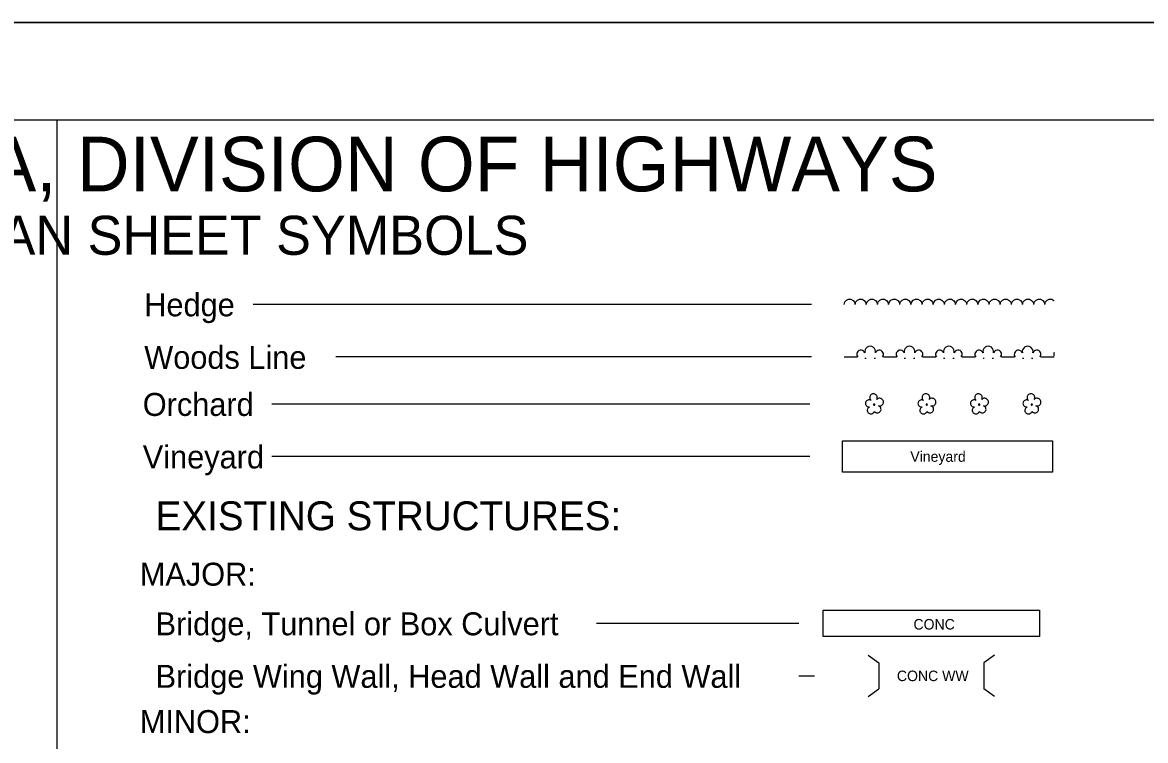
# Model space of a CAD drawing. Extents: x 754056.72 to 754059.56, y 596603.78 to 596605.61.
# Drawn here: x 754058.119 to 754058.839, y 596605.152 to 596605.612 of the extents above; entities that cross this region are included whole.
import ezdxf

# ---------------------------------------------------------------- set-up
doc = ezdxf.new("R2010")
doc.units = 0
for name, color, linetype in [('Sheet_Plan', 7, 'Continuous'), ('Sheet_Plot_Border_Outside_CELL', 7, 'Continuous'), ('Sheet_Symbology', 7, 'Continuous'), ('z - Construction', 7, 'Continuous')]:
    doc.layers.add(name, color=color, linetype=linetype)

msp = doc.modelspace()

# ---------------------------------------------------------------- linework, layer by layer
at = {"layer": 'Sheet_Plan'}
msp.add_line((754059.49567, 596605.54909), (754056.78733, 596605.54909), dxfattribs=at)
at = {"layer": 'Sheet_Plot_Border_Outside_CELL'}
msp.add_lwpolyline([(754056.72484, 596605.61159), (754059.55817, 596605.61159), (754059.55817, 596603.77826), (754056.72484, 596603.77826)], close=True, dxfattribs=at)
at = {"layer": 'Sheet_Symbology'}
for p, q in [((754058.64563, 596605.43106), (754058.64614, 596605.43266)), ((754058.64614, 596605.43266), (754058.64714, 596605.43375)), ((754058.64714, 596605.43375), (754058.64849, 596605.43451)), ((754058.64849, 596605.43451), (754058.65009, 596605.43451)), ((754058.65009, 596605.43451), (754058.65143, 596605.43367)), ((754058.65143, 596605.43367), (754058.65236, 596605.43258)), ((754058.65236, 596605.43258), (754058.65269, 596605.43115)), ((754058.65278, 596605.43106), (754058.65328, 596605.43266)), ((754058.65328, 596605.43266), (754058.65429, 596605.43375)), ((754058.65429, 596605.43375), (754058.65564, 596605.43451)), ((754058.65564, 596605.43451), (754058.65723, 596605.43451)), ((754058.65723, 596605.43451), (754058.65858, 596605.43367)), ((754058.65858, 596605.43367), (754058.6595, 596605.43258)), ((754058.6595, 596605.43258), (754058.65984, 596605.43115)), ((754058.65992, 596605.43106), (754058.66043, 596605.43266)), ((754058.66043, 596605.43266), (754058.66144, 596605.43375)), ((754058.66144, 596605.43375), (754058.66278, 596605.43451)), ((754058.66278, 596605.43451), (754058.66438, 596605.43451)), ((754058.66438, 596605.43451), (754058.66573, 596605.43367)), ((754058.66573, 596605.43367), (754058.66665, 596605.43258)), ((754058.66665, 596605.43258), (754058.66699, 596605.43115)), ((754058.66707, 596605.43106), (754058.66758, 596605.43266)), ((754058.66758, 596605.43266), (754058.66858, 596605.43375)), ((754058.66858, 596605.43375), (754058.66993, 596605.43451)), ((754058.66993, 596605.43451), (754058.67153, 596605.43451)), ((754058.67153, 596605.43451), (754058.67287, 596605.43367)), ((754058.67287, 596605.43367), (754058.6738, 596605.43258)), ((754058.6738, 596605.43258), (754058.67413, 596605.43115)), ((754058.67422, 596605.43106), (754058.67472, 596605.43266)), ((754058.67472, 596605.43266), (754058.67573, 596605.43375)), ((754058.67573, 596605.43375), (754058.67708, 596605.43451)), ((754058.67708, 596605.43451), (754058.67867, 596605.43451)), ((754058.67867, 596605.43451), (754058.68002, 596605.43367)), ((754058.68002, 596605.43367), (754058.68094, 596605.43258)), ((754058.68094, 596605.43258), (754058.68128, 596605.43115)), ((754058.68136, 596605.43106), (754058.68187, 596605.43266)), ((754058.68187, 596605.43266), (754058.68288, 596605.43375)), ((754058.68288, 596605.43375), (754058.68422, 596605.43451)), ((754058.68422, 596605.43451), (754058.68582, 596605.43451)), ((754058.68582, 596605.43451), (754058.68717, 596605.43367)), ((754058.68717, 596605.43367), (754058.68809, 596605.43258)), ((754058.68809, 596605.43258), (754058.68843, 596605.43115)), ((754058.68851, 596605.43106), (754058.68902, 596605.43266)), ((754058.68902, 596605.43266), (754058.69002, 596605.43375)), ((754058.69002, 596605.43375), (754058.69137, 596605.43451)), ((754058.69137, 596605.43451), (754058.69297, 596605.43451)), ((754058.69297, 596605.43451), (754058.69431, 596605.43367)), ((754058.69431, 596605.43367), (754058.69524, 596605.43258)), ((754058.69524, 596605.43258), (754058.69557, 596605.43115)), ((754058.69566, 596605.43106), (754058.69616, 596605.43266)), ((754058.69616, 596605.43266), (754058.69717, 596605.43375)), ((754058.69717, 596605.43375), (754058.69852, 596605.43451)), ((754058.69852, 596605.43451), (754058.70011, 596605.43451)), ((754058.70011, 596605.43451), (754058.70146, 596605.43367)), ((754058.70146, 596605.43367), (754058.70238, 596605.43258)), ((754058.70238, 596605.43258), (754058.70272, 596605.43115)), ((754058.7028, 596605.43106), (754058.70331, 596605.43266)), ((754058.70331, 596605.43266), (754058.70432, 596605.43375)), ((754058.70432, 596605.43375), (754058.70566, 596605.43451)), ((754058.70566, 596605.43451), (754058.70726, 596605.43451)), ((754058.70726, 596605.43451), (754058.70861, 596605.43367)), ((754058.70861, 596605.43367), (754058.70953, 596605.43258)), ((754058.70953, 596605.43258), (754058.70987, 596605.43115)), ((754058.70995, 596605.43106), (754058.71046, 596605.43266)), ((754058.71046, 596605.43266), (754058.71146, 596605.43375)), ((754058.71146, 596605.43375), (754058.71281, 596605.43451)), ((754058.71281, 596605.43451), (754058.71441, 596605.43451)), ((754058.71441, 596605.43451), (754058.71575, 596605.43367)), ((754058.71575, 596605.43367), (754058.71668, 596605.43258)), ((754058.71668, 596605.43258), (754058.71701, 596605.43115)), ((754058.7171, 596605.43106), (754058.7176, 596605.43266)), ((754058.7176, 596605.43266), (754058.71861, 596605.43375)), ((754058.71861, 596605.43375), (754058.71996, 596605.43451)), ((754058.71996, 596605.43451), (754058.72155, 596605.43451)), ((754058.72155, 596605.43451), (754058.7229, 596605.43367)), ((754058.7229, 596605.43367), (754058.72382, 596605.43258)), ((754058.72382, 596605.43258), (754058.72416, 596605.43115)), ((754058.72424, 596605.43106), (754058.72475, 596605.43266)), ((754058.72475, 596605.43266), (754058.72576, 596605.43375)), ((754058.72576, 596605.43375), (754058.7271, 596605.43451)), ((754058.7271, 596605.43451), (754058.7287, 596605.43451)), ((754058.7287, 596605.43451), (754058.73005, 596605.43367)), ((754058.73005, 596605.43367), (754058.73097, 596605.43258)), ((754058.73097, 596605.43258), (754058.73131, 596605.43115)), ((754058.73139, 596605.43106), (754058.7319, 596605.43266)), ((754058.7319, 596605.43266), (754058.7329, 596605.43375)), ((754058.7329, 596605.43375), (754058.73425, 596605.43451)), ((754058.73425, 596605.43451), (754058.73585, 596605.43451)), ((754058.73585, 596605.43451), (754058.73719, 596605.43367)), ((754058.73719, 596605.43367), (754058.73812, 596605.43258)), ((754058.73812, 596605.43258), (754058.73845, 596605.43115)), ((754058.73854, 596605.43106), (754058.73904, 596605.43266)), ((754058.73904, 596605.43266), (754058.74005, 596605.43375)), ((754058.74005, 596605.43375), (754058.7414, 596605.43451)), ((754058.7414, 596605.43451), (754058.74299, 596605.43451)), ((754058.74299, 596605.43451), (754058.74434, 596605.43367)), ((754058.74434, 596605.43367), (754058.74526, 596605.43258)), ((754058.74526, 596605.43258), (754058.7456, 596605.43115)), ((754058.74568, 596605.43106), (754058.74619, 596605.43266)), ((754058.74619, 596605.43266), (754058.7472, 596605.43375)), ((754058.7472, 596605.43375), (754058.74854, 596605.43451)), ((754058.74854, 596605.43451), (754058.75014, 596605.43451)), ((754058.75014, 596605.43451), (754058.75149, 596605.43367)), ((754058.75149, 596605.43367), (754058.75241, 596605.43258)), ((754058.75241, 596605.43258), (754058.75275, 596605.43115)), ((754058.75283, 596605.43106), (754058.75334, 596605.43266)), ((754058.75334, 596605.43266), (754058.75434, 596605.43375)), ((754058.75434, 596605.43375), (754058.75569, 596605.43451)), ((754058.75569, 596605.43451), (754058.75729, 596605.43451)), ((754058.75729, 596605.43451), (754058.75863, 596605.43367)), ((754058.75863, 596605.43367), (754058.75956, 596605.43258)), ((754058.75956, 596605.43258), (754058.75989, 596605.43115)), ((754058.75998, 596605.43106), (754058.76048, 596605.43266)), ((754058.76048, 596605.43266), (754058.76149, 596605.43375)), ((754058.76149, 596605.43375), (754058.76284, 596605.43451)), ((754058.76284, 596605.43451), (754058.76443, 596605.43451)), ((754058.76443, 596605.43451), (754058.76578, 596605.43367)), ((754058.76578, 596605.43367), (754058.7667, 596605.43258)), ((754058.7667, 596605.43258), (754058.76704, 596605.43115)), ((754058.76712, 596605.43106), (754058.76763, 596605.43266)), ((754058.76763, 596605.43266), (754058.76864, 596605.43375)), ((754058.76864, 596605.43375), (754058.76998, 596605.43451)), ((754058.76998, 596605.43451), (754058.77158, 596605.43451)), ((754058.77158, 596605.43451), (754058.77293, 596605.43367)), ((754058.77293, 596605.43367), (754058.77385, 596605.43258)), ((754058.77385, 596605.43258), (754058.77419, 596605.43115)), ((754058.77427, 596605.43106), (754058.77478, 596605.43266)), ((754058.77478, 596605.43266), (754058.77578, 596605.43375)), ((754058.77578, 596605.43375), (754058.77713, 596605.43451)), ((754058.77713, 596605.43451), (754058.77873, 596605.43451)), ((754058.77873, 596605.43451), (754058.78007, 596605.43367)), ((754058.78007, 596605.43367), (754058.78016, 596605.43359)), ((754058.62479, 596605.43106), (754058.26714, 596605.43106)), ((754058.62479, 596605.39743), (754058.32022, 596605.39743)), ((754058.64563, 596605.39743), (754058.65404, 596605.39743)), ((754058.659, 596605.39659), (754058.65984, 596605.39659)), ((754058.66489, 596605.39659), (754058.66573, 596605.39659)), ((754058.67085, 596605.39743), (754058.67926, 596605.39743)), ((754058.68422, 596605.39659), (754058.68506, 596605.39659)), ((754058.69011, 596605.39659), (754058.69095, 596605.39659)), ((754058.69608, 596605.39743), (754058.70449, 596605.39743)), ((754058.70945, 596605.39659), (754058.71029, 596605.39659)), ((754058.71533, 596605.39659), (754058.71617, 596605.39659)), ((754058.7213, 596605.39743), (754058.72971, 596605.39743)), ((754058.73467, 596605.39659), (754058.73551, 596605.39659)), ((754058.74056, 596605.39659), (754058.7414, 596605.39659)), ((754058.74653, 596605.39743), (754058.75493, 596605.39743)), ((754058.75989, 596605.39659), (754058.76073, 596605.39659)), ((754058.76578, 596605.39659), (754058.76662, 596605.39659)), ((754058.77175, 596605.39743), (754058.78016, 596605.39743)), ((754058.62384, 596605.36729), (754058.27923, 596605.36729)), ((754058.62384, 596605.33366), (754058.27923, 596605.33366)), ((754058.61659, 596605.22687), (754058.48716, 596605.22687)), ((754058.66106, 596605.20646), (754058.66796, 596605.20164)), ((754058.66796, 596605.20164), (754058.66796, 596605.18483)), ((754058.74211, 596605.20646), (754058.73522, 596605.20164)), ((754058.73522, 596605.20164), (754058.73522, 596605.18483)), ((754058.61659, 596605.19323), (754058.62665, 596605.19323)), ((754058.66106, 596605.18001), (754058.66796, 596605.18483)), ((754058.74211, 596605.18001), (754058.73522, 596605.18483))]:
    msp.add_line(p, q, dxfattribs=at)
for points in [[(754058.66663, 596605.37023), (754058.66688, 596605.37073), (754058.66696, 596605.37124), (754058.66688, 596605.37174), (754058.66679, 596605.37225), (754058.66654, 596605.37267), (754058.66629, 596605.37309), (754058.66587, 596605.37342), (754058.66545, 596605.37368), (754058.66486, 596605.37384), (754058.66444, 596605.37384), (754058.66393, 596605.37376), (754058.66343, 596605.37359), (754058.66301, 596605.37334), (754058.66259, 596605.373), (754058.66234, 596605.3725), (754058.66217, 596605.37208), (754058.66208, 596605.37157), (754058.66208, 596605.37107), (754058.66217, 596605.37057), (754058.66242, 596605.37014), (754058.66276, 596605.36964), (754058.66234, 596605.36989), (754058.66183, 596605.36998), (754058.66133, 596605.36998), (754058.66091, 596605.36981), (754058.66049, 596605.36964), (754058.66007, 596605.3693), (754058.65973, 596605.36897), (754058.65948, 596605.36855), (754058.65939, 596605.36813), (754058.65931, 596605.36754), (754058.65939, 596605.36712), (754058.65956, 596605.3667), (754058.6599, 596605.36628), (754058.66015, 596605.36594), (754058.66057, 596605.36569), (754058.66108, 596605.36544), (754058.6615, 596605.36535), (754058.662, 596605.36535), (754058.66158, 596605.36518), (754058.66116, 596605.36485), (754058.66091, 596605.36451), (754058.66074, 596605.36401), (754058.66057, 596605.3635), (754058.66057, 596605.36308), (754058.66066, 596605.36258), (754058.66091, 596605.36216), (754058.66116, 596605.36174), (754058.6615, 596605.3614), (754058.66192, 596605.36115), (754058.66234, 596605.36098), (754058.66284, 596605.36098), (754058.66335, 596605.36098), (754058.66377, 596605.36106), (754058.66419, 596605.3614), (754058.66461, 596605.36165), (754058.66503, 596605.36241)], [(754058.70026, 596605.37023), (754058.70051, 596605.37073), (754058.70059, 596605.37124), (754058.70051, 596605.37174), (754058.70042, 596605.37225), (754058.70017, 596605.37267), (754058.69992, 596605.37309), (754058.6995, 596605.37342), (754058.69908, 596605.37368), (754058.69849, 596605.37384), (754058.69807, 596605.37384), (754058.69757, 596605.37376), (754058.69706, 596605.37359), (754058.69664, 596605.37334), (754058.69622, 596605.373), (754058.69597, 596605.3725), (754058.6958, 596605.37208), (754058.69572, 596605.37157), (754058.69572, 596605.37107), (754058.6958, 596605.37057), (754058.69605, 596605.37014), (754058.69639, 596605.36964), (754058.69597, 596605.36989), (754058.69546, 596605.36998), (754058.69496, 596605.36998), (754058.69454, 596605.36981), (754058.69412, 596605.36964), (754058.6937, 596605.3693), (754058.69336, 596605.36897), (754058.69311, 596605.36855), (754058.69303, 596605.36813), (754058.69294, 596605.36754), (754058.69303, 596605.36712), (754058.69319, 596605.3667), (754058.69353, 596605.36628), (754058.69378, 596605.36594), (754058.6942, 596605.36569), (754058.69471, 596605.36544), (754058.69513, 596605.36535), (754058.69563, 596605.36535), (754058.69521, 596605.36518), (754058.69479, 596605.36485), (754058.69454, 596605.36451), (754058.69437, 596605.36401), (754058.6942, 596605.3635), (754058.6942, 596605.36308), (754058.69429, 596605.36258), (754058.69454, 596605.36216), (754058.69479, 596605.36174), (754058.69513, 596605.3614), (754058.69555, 596605.36115), (754058.69597, 596605.36098), (754058.69647, 596605.36098), (754058.69698, 596605.36098), (754058.6974, 596605.36106), (754058.69782, 596605.3614), (754058.69824, 596605.36165), (754058.69866, 596605.36241)], [(754058.73389, 596605.37023), (754058.73414, 596605.37073), (754058.73422, 596605.37124), (754058.73414, 596605.37174), (754058.73406, 596605.37225), (754058.7338, 596605.37267), (754058.73355, 596605.37309), (754058.73313, 596605.37342), (754058.73271, 596605.37368), (754058.73212, 596605.37384), (754058.7317, 596605.37384), (754058.7312, 596605.37376), (754058.73069, 596605.37359), (754058.73027, 596605.37334), (754058.72985, 596605.373), (754058.7296, 596605.3725), (754058.72943, 596605.37208), (754058.72935, 596605.37157), (754058.72935, 596605.37107), (754058.72943, 596605.37057), (754058.72968, 596605.37014), (754058.73002, 596605.36964), (754058.7296, 596605.36989), (754058.7291, 596605.36998), (754058.72859, 596605.36998), (754058.72817, 596605.36981), (754058.72775, 596605.36964), (754058.72733, 596605.3693), (754058.72699, 596605.36897), (754058.72674, 596605.36855), (754058.72666, 596605.36813), (754058.72657, 596605.36754), (754058.72666, 596605.36712), (754058.72683, 596605.3667), (754058.72716, 596605.36628), (754058.72741, 596605.36594), (754058.72783, 596605.36569), (754058.72834, 596605.36544), (754058.72876, 596605.36535), (754058.72926, 596605.36535), (754058.72884, 596605.36518), (754058.72842, 596605.36485), (754058.72817, 596605.36451), (754058.728, 596605.36401), (754058.72783, 596605.3635), (754058.72783, 596605.36308), (754058.72792, 596605.36258), (754058.72817, 596605.36216), (754058.72842, 596605.36174), (754058.72876, 596605.3614), (754058.72918, 596605.36115), (754058.7296, 596605.36098), (754058.7301, 596605.36098), (754058.73061, 596605.36098), (754058.73103, 596605.36106), (754058.73145, 596605.3614), (754058.73187, 596605.36165), (754058.73229, 596605.36241)], [(754058.76752, 596605.37023), (754058.76777, 596605.37073), (754058.76786, 596605.37124), (754058.76777, 596605.37174), (754058.76769, 596605.37225), (754058.76743, 596605.37267), (754058.76718, 596605.37309), (754058.76676, 596605.37342), (754058.76634, 596605.37368), (754058.76575, 596605.37384), (754058.76533, 596605.37384), (754058.76483, 596605.37376), (754058.76432, 596605.37359), (754058.7639, 596605.37334), (754058.76348, 596605.373), (754058.76323, 596605.3725), (754058.76306, 596605.37208), (754058.76298, 596605.37157), (754058.76298, 596605.37107), (754058.76306, 596605.37057), (754058.76331, 596605.37014), (754058.76365, 596605.36964), (754058.76323, 596605.36989), (754058.76273, 596605.36998), (754058.76222, 596605.36998), (754058.7618, 596605.36981), (754058.76138, 596605.36964), (754058.76096, 596605.3693), (754058.76062, 596605.36897), (754058.76037, 596605.36855), (754058.76029, 596605.36813), (754058.7602, 596605.36754), (754058.76029, 596605.36712), (754058.76046, 596605.3667), (754058.76079, 596605.36628), (754058.76104, 596605.36594), (754058.76147, 596605.36569), (754058.76197, 596605.36544), (754058.76239, 596605.36535), (754058.76289, 596605.36535), (754058.76247, 596605.36518), (754058.76205, 596605.36485), (754058.7618, 596605.36451), (754058.76163, 596605.36401), (754058.76147, 596605.3635), (754058.76147, 596605.36308), (754058.76155, 596605.36258), (754058.7618, 596605.36216), (754058.76205, 596605.36174), (754058.76239, 596605.3614), (754058.76281, 596605.36115), (754058.76323, 596605.36098), (754058.76374, 596605.36098), (754058.76424, 596605.36098), (754058.76466, 596605.36106), (754058.76508, 596605.3614), (754058.7655, 596605.36165), (754058.76592, 596605.36241)], [(754058.6652, 596605.36729), (754058.66494, 596605.36729), (754058.66478, 596605.3672), (754058.66461, 596605.36712), (754058.66461, 596605.36687), (754058.66461, 596605.3667), (754058.66478, 596605.36653), (754058.66503, 596605.36653), (754058.6652, 596605.36653), (754058.66536, 596605.3667), (754058.66545, 596605.36695), (754058.66536, 596605.36712), (754058.6652, 596605.36729)], [(754058.66503, 596605.36241), (754058.66604, 596605.36182), (754058.66654, 596605.36165), (754058.66705, 596605.36157), (754058.66755, 596605.36165), (754058.66797, 596605.36182), (754058.66839, 596605.36207), (754058.66881, 596605.36241), (754058.66906, 596605.36283), (754058.66923, 596605.36325), (754058.6694, 596605.36376), (754058.66932, 596605.36426), (754058.66923, 596605.36476), (754058.6689, 596605.36527), (754058.66864, 596605.3656), (754058.66822, 596605.36586), (754058.66772, 596605.36611), (754058.66822, 596605.36603), (754058.66881, 596605.36603), (754058.66923, 596605.36619), (754058.66974, 596605.36645), (754058.67016, 596605.3667), (754058.67049, 596605.36712), (754058.67074, 596605.36762), (754058.67083, 596605.36813), (754058.67091, 596605.36863), (754058.67083, 596605.36914), (754058.67066, 596605.36964), (754058.67032, 596605.37006), (754058.6699, 596605.37048), (754058.66948, 596605.37073), (754058.66898, 596605.3709), (754058.66847, 596605.37099), (754058.66797, 596605.37099), (754058.66747, 596605.37082), (754058.66705, 596605.37057), (754058.66663, 596605.37023)], [(754058.69883, 596605.36729), (754058.69857, 596605.36729), (754058.69841, 596605.3672), (754058.69824, 596605.36712), (754058.69824, 596605.36687), (754058.69824, 596605.3667), (754058.69841, 596605.36653), (754058.69866, 596605.36653), (754058.69883, 596605.36653), (754058.699, 596605.3667), (754058.69908, 596605.36695), (754058.699, 596605.36712), (754058.69883, 596605.36729)], [(754058.69866, 596605.36241), (754058.69967, 596605.36182), (754058.70017, 596605.36165), (754058.70068, 596605.36157), (754058.70118, 596605.36165), (754058.7016, 596605.36182), (754058.70202, 596605.36207), (754058.70244, 596605.36241), (754058.70269, 596605.36283), (754058.70286, 596605.36325), (754058.70303, 596605.36376), (754058.70295, 596605.36426), (754058.70286, 596605.36476), (754058.70253, 596605.36527), (754058.70227, 596605.3656), (754058.70185, 596605.36586), (754058.70135, 596605.36611), (754058.70185, 596605.36603), (754058.70244, 596605.36603), (754058.70286, 596605.36619), (754058.70337, 596605.36645), (754058.70379, 596605.3667), (754058.70412, 596605.36712), (754058.70438, 596605.36762), (754058.70446, 596605.36813), (754058.70454, 596605.36863), (754058.70446, 596605.36914), (754058.70429, 596605.36964), (754058.70396, 596605.37006), (754058.70354, 596605.37048), (754058.70312, 596605.37073), (754058.70261, 596605.3709), (754058.70211, 596605.37099), (754058.7016, 596605.37099), (754058.7011, 596605.37082), (754058.70068, 596605.37057), (754058.70026, 596605.37023)], [(754058.73246, 596605.36729), (754058.73221, 596605.36729), (754058.73204, 596605.3672), (754058.73187, 596605.36712), (754058.73187, 596605.36687), (754058.73187, 596605.3667), (754058.73204, 596605.36653), (754058.73229, 596605.36653), (754058.73246, 596605.36653), (754058.73263, 596605.3667), (754058.73271, 596605.36695), (754058.73263, 596605.36712), (754058.73246, 596605.36729)], [(754058.73229, 596605.36241), (754058.7333, 596605.36182), (754058.7338, 596605.36165), (754058.73431, 596605.36157), (754058.73481, 596605.36165), (754058.73523, 596605.36182), (754058.73565, 596605.36207), (754058.73607, 596605.36241), (754058.73633, 596605.36283), (754058.73649, 596605.36325), (754058.73666, 596605.36376), (754058.73658, 596605.36426), (754058.73649, 596605.36476), (754058.73616, 596605.36527), (754058.73591, 596605.3656), (754058.73549, 596605.36586), (754058.73498, 596605.36611), (754058.73549, 596605.36603), (754058.73607, 596605.36603), (754058.73649, 596605.36619), (754058.737, 596605.36645), (754058.73742, 596605.3667), (754058.73776, 596605.36712), (754058.73801, 596605.36762), (754058.73809, 596605.36813), (754058.73818, 596605.36863), (754058.73809, 596605.36914), (754058.73792, 596605.36964), (754058.73759, 596605.37006), (754058.73717, 596605.37048), (754058.73675, 596605.37073), (754058.73624, 596605.3709), (754058.73574, 596605.37099), (754058.73523, 596605.37099), (754058.73473, 596605.37082), (754058.73431, 596605.37057), (754058.73389, 596605.37023)], [(754058.76609, 596605.36729), (754058.76584, 596605.36729), (754058.76567, 596605.3672), (754058.7655, 596605.36712), (754058.7655, 596605.36687), (754058.7655, 596605.3667), (754058.76567, 596605.36653), (754058.76592, 596605.36653), (754058.76609, 596605.36653), (754058.76626, 596605.3667), (754058.76634, 596605.36695), (754058.76626, 596605.36712), (754058.76609, 596605.36729)], [(754058.76592, 596605.36241), (754058.76693, 596605.36182), (754058.76743, 596605.36165), (754058.76794, 596605.36157), (754058.76844, 596605.36165), (754058.76886, 596605.36182), (754058.76928, 596605.36207), (754058.7697, 596605.36241), (754058.76996, 596605.36283), (754058.77013, 596605.36325), (754058.77029, 596605.36376), (754058.77021, 596605.36426), (754058.77013, 596605.36476), (754058.76979, 596605.36527), (754058.76954, 596605.3656), (754058.76912, 596605.36586), (754058.76861, 596605.36611), (754058.76912, 596605.36603), (754058.7697, 596605.36603), (754058.77013, 596605.36619), (754058.77063, 596605.36645), (754058.77105, 596605.3667), (754058.77139, 596605.36712), (754058.77164, 596605.36762), (754058.77172, 596605.36813), (754058.77181, 596605.36863), (754058.77172, 596605.36914), (754058.77155, 596605.36964), (754058.77122, 596605.37006), (754058.7708, 596605.37048), (754058.77038, 596605.37073), (754058.76987, 596605.3709), (754058.76937, 596605.37099), (754058.76886, 596605.37099), (754058.76836, 596605.37082), (754058.76794, 596605.37057), (754058.76752, 596605.37023)], [(754058.64468, 596605.34374), (754058.77921, 596605.34374), (754058.77921, 596605.32357), (754058.64468, 596605.32357), (754058.64468, 596605.34374)], [(754058.63222, 596605.23527), (754058.77095, 596605.23527), (754058.77095, 596605.21846), (754058.63222, 596605.21846), (754058.63222, 596605.23527)]]:
    msp.add_lwpolyline(points, dxfattribs=at)
for centre, radius, start, end in [((754058.66236, 596605.40082), 0.00347, 345.96376, 194.03624), ((754058.68758, 596605.40082), 0.00347, 345.96376, 194.03624), ((754058.71281, 596605.40082), 0.00347, 345.96376, 194.03624), ((754058.73803, 596605.40082), 0.00347, 345.96376, 194.03624), ((754058.76325, 596605.40082), 0.00347, 345.96376, 194.03624), ((754058.65648, 596605.39914), 0.00266, 18.43495, 219.23152), ((754058.66825, 596605.39914), 0.00266, 320.76848, 161.56505), ((754058.6817, 596605.39914), 0.00266, 18.43495, 219.23152), ((754058.69347, 596605.39914), 0.00266, 320.76848, 161.56505), ((754058.70692, 596605.39914), 0.00266, 18.43495, 219.23152), ((754058.71869, 596605.39914), 0.00266, 320.76848, 161.56505), ((754058.73214, 596605.39914), 0.00266, 18.43495, 219.23152), ((754058.74391, 596605.39914), 0.00266, 320.76848, 161.56505), ((754058.75737, 596605.39914), 0.00266, 18.43495, 219.23152), ((754058.76914, 596605.39914), 0.00266, 320.76848, 161.56505), ((754058.78259, 596605.39914), 0.00266, 156.25102, 203.74899)]:
    msp.add_arc(centre, radius, start, end, dxfattribs=at)
at = {"layer": 'z - Construction'}
for p, q in [((754059.55817, 596605.61159), (754056.72484, 596605.61159)), ((754058.1415, 596605.54909), (754058.14146, 596603.84076))]:
    msp.add_line(p, q, dxfattribs=at)

# ---------------------------------------------------------------- texts
at = {"layer": 'Sheet_Symbology'}
for s, height, p in [('STATE OF NORTH CAROLINA, DIVISION OF HIGHWAYS', 0.035, (754057.46774, 596605.50345)), ('CONVENTIONAL  PLAN SHEET SYMBOLS', 0.025, (754057.78215, 596605.46284)), ('Hedge', 0.014714, (754058.1974, 596605.42345)), ('Woods Line', 0.014714, (754058.1974, 596605.38982)), ('Orchard', 0.014714, (754058.19645, 596605.35968)), ('Vineyard', 0.014714, (754058.19645, 596605.32605)), ('EXISTING STRUCTURES:', 0.0184972, (754058.20467, 596605.28648)), ('MAJOR:', 0.014714, (754058.19453, 596605.25097)), ('Bridge, Tunnel or Box Culvert', 0.0147137, (754058.20467, 596605.21921)), ('CONC', 0.006726, (754058.69013, 596605.22289)), ('Bridge Wing Wall, Head Wall and End Wall', 0.0147137, (754058.20467, 596605.18558)), ('MINOR:', 0.014714, (754058.19453, 596605.1566))]:
    msp.add_text(s, height=height, dxfattribs=at).set_placement(p)
for s, p in [('Vineyard', (754058.68811, 596605.33029)), ('CONC WW', (754058.67952, 596605.18987))]:
    msp.add_text(s, height=0.006726, rotation=0.00002, dxfattribs=at).set_placement(p)

doc.saveas('drawing.dxf')
